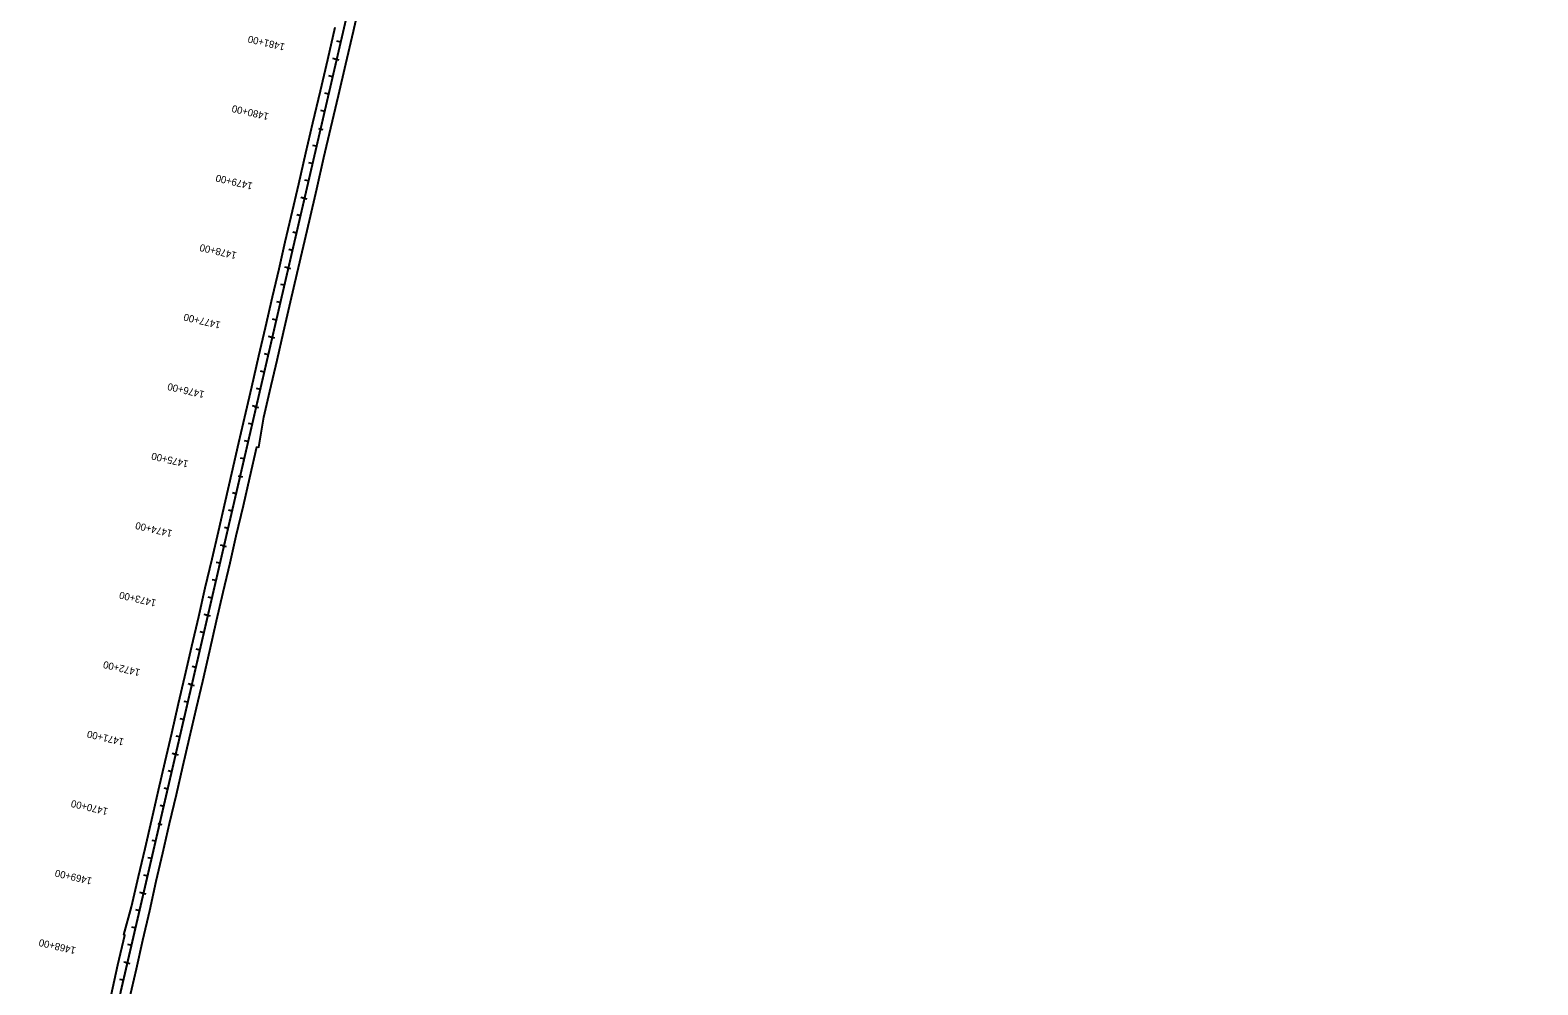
# Model space of a CAD drawing. Extents: x 21596470 to 21601942, y 8263806 to 8275912.
# Drawn here: x 21596601 to 21598714, y 8267212 to 8268550 of the extents above; entities that cross this region are included whole.
import ezdxf

# ---------------------------------------------------------------- set-up
doc = ezdxf.new("R2010")
doc.units = 0
for name, color, linetype in [('Level 1', 7, 'Continuous'), ('Level 20', 7, 'Continuous'), ('SurTxtLeaderLine', 7, 'Continuous'), ('SurTxtSurveyInformation', 7, 'Continuous'), ('wetNoteSoil', 7, 'Continuous')]:
    doc.layers.add(name, color=color, linetype=linetype)

msp = doc.modelspace()

# ---------------------------------------------------------------- linework, layer by layer
at = {"layer": 'Level 1'}
for p, q in [((21597031.1, 8268509.5), (21597025.7, 8268510.7)), ((21597005.5, 8268412.7), (21597011.5, 8268411.4)), ((21596986, 8268314.6), (21596980.7, 8268315.8)), ((21596963.4, 8268217.2), (21596958.1, 8268218.4)), ((21596940.9, 8268119.8), (21596935.6, 8268121)), ((21596918.4, 8268022.3), (21596913.1, 8268023.6)), ((21596892.8, 8267925.6), (21596898.8, 8267924.2)), ((21596873.3, 8267827.5), (21596868, 8267828.7)), ((21596850.8, 8267730.1), (21596845.4, 8267731.3)), ((21596828.2, 8267632.6), (21596822.9, 8267633.9)), ((21596805.7, 8267535.2), (21596800.4, 8267536.4)), ((21596780.2, 8267438.5), (21596786.1, 8267437.1)), ((21596760.6, 8267340.3), (21596755.3, 8267341.6)), ((21596738.1, 8267242.9), (21596732.7, 8267244.1))]:
    msp.add_line(p, q, dxfattribs=at)
at = {"layer": 'Level 20'}
for p, q in [((21596601.4, 8266652.3), (21598714.2, 8275785)), ((21596728.7, 8267202.6), (21598588.8, 8275242.6))]:
    msp.add_line(p, q, dxfattribs=at)
at = {"layer": 'SurTxtLeaderLine'}
msp.add_lwpolyline([(21596740.4, 8267192.7), (21596750.3, 8267234.8), (21596759.2, 8267274.8), (21596769, 8267316.4), (21596778.2, 8267357.6), (21596787.4, 8267397.4), (21596796.9, 8267438.5), (21596806.4, 8267479.2), (21596815.5, 8267518.4), (21596824.9, 8267558.4), (21596834.5, 8267600.3), (21596843.3, 8267637.8), (21596853.3, 8267680.8), (21596862.7, 8267722.5), (21596871.8, 8267762.5), (21596881.6, 8267803.8), (21596890.2, 8267841.4), (21596900.2, 8267883.9), (21596909.3, 8267923.4), (21596919.2, 8267966.2), (21596921.9, 8267965.7), (21596928.9, 8268007.9), (21596937.3, 8268044.5), (21596947.6, 8268087.9), (21596956.5, 8268127), (21596966.4, 8268169.8), (21596975.8, 8268210), (21596984.4, 8268247.5), (21596992.8, 8268283.4), (21597003.1, 8268328.1), (21597013.1, 8268371.7), (21597022.7, 8268413.5), (21597033.4, 8268459), (21597043.6, 8268503.3), (21597054.4, 8268549), (21597064.4, 8268592.7)], dxfattribs=at)
at = {"layer": 'SurTxtSurveyInformation'}
msp.add_lwpolyline([(21596715, 8267197.4), (21596724.5, 8267240), (21596734, 8267281.8), (21596732.5, 8267282.2), (21596743.4, 8267321.6), (21596753.2, 8267363.9), (21596762.4, 8267403.5), (21596771.7, 8267444.1), (21596781.5, 8267485), (21596790.8, 8267525.1), (21596800, 8267564.9), (21596809.5, 8267606.4), (21596818.3, 8267644.4), (21596827.9, 8267686.8), (21596837.6, 8267728.6), (21596846.9, 8267768.9), (21596856.4, 8267809.5), (21596865.3, 8267847.5), (21596875.2, 8267890.5), (21596884, 8267929.5), (21596894, 8267972.2), (21596903.6, 8268014.4), (21596912, 8268050.4), (21596922.1, 8268093.8), (21596931.4, 8268133.8), (21596941.1, 8268176.7), (21596950.3, 8268215.9), (21596958.8, 8268253.7), (21596967.3, 8268289.2), (21596977.8, 8268334.8), (21596987.9, 8268378.3), (21596997.7, 8268420.5), (21597008.1, 8268465.5), (21597018.4, 8268509.5), (21597028.9, 8268554.8)], dxfattribs=at)
at = {"layer": 'wetNoteSoil'}
for p, q in [((21597036.7, 8268533.8), (21597031.4, 8268535.1)), ((21597028.1, 8268510.2), (21597034, 8268508.8)), ((21597025.4, 8268485.1), (21597020.1, 8268486.3)), ((21597019.8, 8268460.8), (21597014.5, 8268462)), ((21597014.2, 8268436.4), (21597008.8, 8268437.6)), ((21597005.5, 8268412.7), (21597011.5, 8268411.4)), ((21597002.9, 8268387.7), (21596997.6, 8268388.9)), ((21596997.3, 8268363.3), (21596991.9, 8268364.6)), ((21596991.6, 8268339), (21596986.3, 8268340.2)), ((21596983, 8268315.3), (21596989, 8268313.9)), ((21596980.4, 8268290.3), (21596975, 8268291.5)), ((21596974.7, 8268265.9), (21596969.4, 8268267.1)), ((21596969.1, 8268241.5), (21596963.8, 8268242.8)), ((21596960.5, 8268217.9), (21596966.4, 8268216.5)), ((21596957.8, 8268192.8), (21596952.5, 8268194.1)), ((21596952.2, 8268168.5), (21596946.9, 8268169.7)), ((21596946.5, 8268144.1), (21596941.2, 8268145.3)), ((21596937.9, 8268120.5), (21596943.9, 8268119.1)), ((21596935.3, 8268095.4), (21596930, 8268096.6)), ((21596929.6, 8268071), (21596924.3, 8268072.3)), ((21596924, 8268046.7), (21596918.7, 8268047.9)), ((21596915.4, 8268023), (21596921.4, 8268021.6)), ((21596912.7, 8267998), (21596907.4, 8267999.2)), ((21596907.1, 8267973.6), (21596901.8, 8267974.9)), ((21596901.5, 8267949.3), (21596896.1, 8267950.5)), ((21596892.8, 8267925.6), (21596898.8, 8267924.2)), ((21596890.2, 8267900.6), (21596884.9, 8267901.8)), ((21596884.6, 8267876.2), (21596879.2, 8267877.4)), ((21596878.9, 8267851.8), (21596873.6, 8267853.1)), ((21596870.3, 8267828.2), (21596876.3, 8267826.8)), ((21596867.7, 8267803.1), (21596862.3, 8267804.4)), ((21596862, 8267778.8), (21596856.7, 8267780)), ((21596856.4, 8267754.4), (21596851.1, 8267755.6)), ((21596847.8, 8267730.7), (21596853.7, 8267729.4)), ((21596845.1, 8267705.7), (21596839.8, 8267706.9)), ((21596839.5, 8267681.3), (21596834.2, 8267682.6)), ((21596833.8, 8267657), (21596828.5, 8267658.2)), ((21596825.2, 8267633.3), (21596831.2, 8267631.9)), ((21596822.6, 8267608.3), (21596817.3, 8267609.5)), ((21596816.9, 8267583.9), (21596811.6, 8267585.1)), ((21596811.3, 8267559.6), (21596806, 8267560.8)), ((21596802.7, 8267535.9), (21596808.7, 8267534.5)), ((21596800, 8267510.8), (21596794.7, 8267512.1)), ((21596794.4, 8267486.5), (21596789.1, 8267487.7)), ((21596788.8, 8267462.1), (21596783.4, 8267463.4)), ((21596780.2, 8267438.5), (21596786.1, 8267437.1)), ((21596777.5, 8267413.4), (21596772.2, 8267414.6)), ((21596771.9, 8267389.1), (21596766.5, 8267390.3)), ((21596766.2, 8267364.7), (21596760.9, 8267365.9)), ((21596757.6, 8267341), (21596763.6, 8267339.7)), ((21596755, 8267316), (21596749.6, 8267317.2)), ((21596749.3, 8267291.6), (21596744, 8267292.9)), ((21596743.7, 8267267.3), (21596738.4, 8267268.5)), ((21596735.1, 8267243.6), (21596741, 8267242.2)), ((21596732.4, 8267218.6), (21596727.1, 8267219.8))]:
    msp.add_line(p, q, dxfattribs=at)

# ---------------------------------------------------------------- texts
at = {"layer": 'Level 1'}
for s, p in [('1480+00', (21596936.6, 8268433.8)), ('1475+00', (21596823.9, 8267946.7)), ('1470+00', (21596711.2, 8267459.6))]:
    msp.add_text(s, height=10.02, rotation=166.974, dxfattribs=at).set_placement(p)
at = {"layer": 'wetNoteSoil'}
for s, p in [('1481+00', (21596959.1, 8268531.3)), ('1480+00', (21596936.6, 8268433.8)), ('1479+00', (21596914, 8268336.4)), ('1478+00', (21596891.5, 8268239)), ('1477+00', (21596869, 8268141.5)), ('1476+00', (21596846.4, 8268044.1)), ('1475+00', (21596823.9, 8267946.7)), ('1474+00', (21596801.4, 8267849.3)), ('1473+00', (21596778.8, 8267751.8)), ('1472+00', (21596756.3, 8267654.4)), ('1471+00', (21596733.7, 8267557)), ('1470+00', (21596711.2, 8267459.6)), ('1469+00', (21596688.7, 8267362.1)), ('1468+00', (21596666.1, 8267264.7))]:
    msp.add_text(s, height=10.02, rotation=166.974, dxfattribs=at).set_placement(p)

doc.saveas('drawing.dxf')
